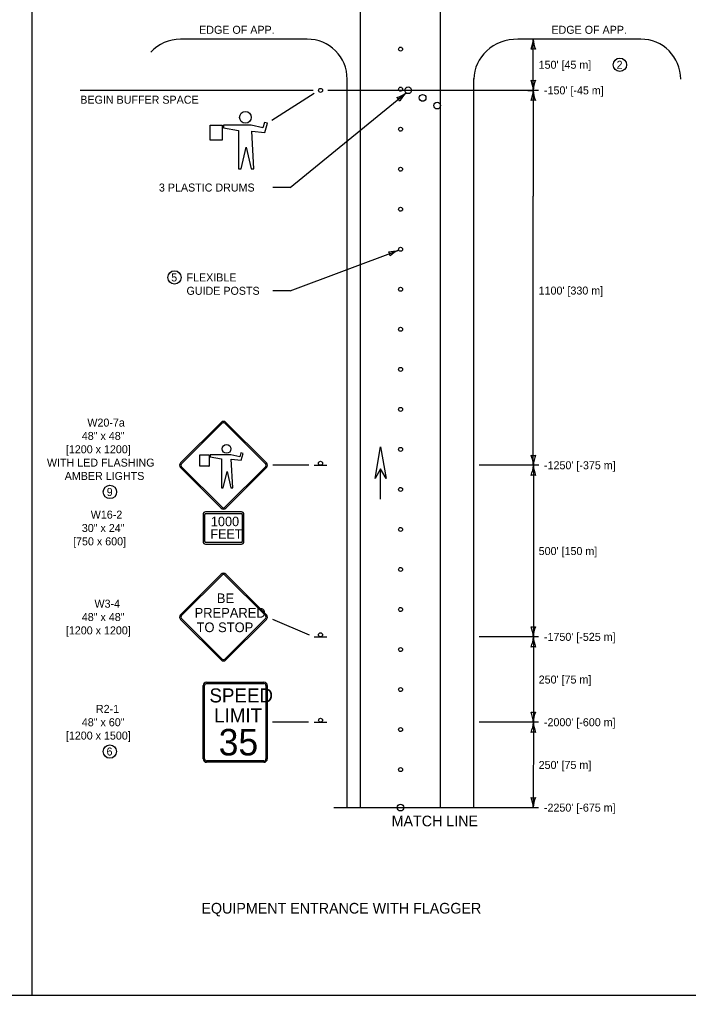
# Model space of a CAD drawing. Extents: x 49991.4 to 50021, y 49987.6 to 50011.4.
# Drawn here: x 50009.09 to 50014.11, y 49987.8 to 49995.11 of the extents above; entities that cross this region are included whole.
import ezdxf

# ---------------------------------------------------------------- set-up
doc = ezdxf.new("R2010")
doc.units = 0
for name, color, linetype in [('Level 1', 7, 'Continuous'), ('Level 2', 7, 'Continuous'), ('Level 3', 7, 'Continuous'), ('Level 6', 7, 'Continuous')]:
    doc.layers.add(name, color=color, linetype=linetype)

msp = doc.modelspace()

# ---------------------------------------------------------------- linework, layer by layer
at = {"layer": 'Level 1'}
for p, q in [((50011.6491, 49989.2068), (50011.6491, 49998.1941)), ((50012.2491, 49989.2068), (50012.2491, 49998.1941)), ((50011.2489, 49994.9668), (50010.2983, 49994.9668)), ((50013.7497, 49994.9668), (50012.8291, 49994.9668)), ((50011.5491, 49989.2068), (50011.5491, 49994.6668)), ((50012.4991, 49989.2068), (50012.4991, 49994.6713)), ((50010.5205, 49994.2099), (50010.5205, 49994.3224)), ((50010.5205, 49994.3224), (50010.6124, 49994.3224)), ((50010.6124, 49994.3224), (50010.6124, 49994.2099)), ((50010.8296, 49994.3217), (50010.6227, 49994.3217)), ((50010.6227, 49994.3217), (50010.6227, 49994.3031)), ((50010.6227, 49994.3031), (50010.7352, 49994.2809)), ((50010.7352, 49994.2809), (50010.7352, 49993.9946)), ((50010.9164, 49994.3017), (50010.8296, 49994.3217)), ((50010.8483, 49993.9946), (50010.8335, 49994.278)), ((50010.8335, 49994.278), (50010.9311, 49994.267)), ((50010.9291, 49994.3413), (50010.9164, 49994.3017)), ((50010.9511, 49994.3358), (50010.9291, 49994.3413)), ((50010.9311, 49994.267), (50010.9511, 49994.3358)), ((50010.6124, 49994.2099), (50010.5205, 49994.2099)), ((50010.7534, 49993.9946), (50010.7917, 49994.1559)), ((50010.7917, 49994.1559), (50010.83, 49993.9946)), ((50010.7352, 49993.9946), (50010.7534, 49993.9946)), ((50010.83, 49993.9946), (50010.8483, 49993.9946)), ((50010.6042, 49992.0945), (50010.3001, 49991.7905)), ((50010.6112, 49992.0875), (50010.3072, 49991.7834)), ((50010.9365, 49991.7834), (50010.6325, 49992.0875)), ((50010.9436, 49991.7905), (50010.6395, 49992.0945)), ((50010.7525, 49991.8662), (50010.7429, 49991.8362)), ((50010.7691, 49991.862), (50010.7525, 49991.8662)), ((50010.4435, 49991.7668), (50010.4435, 49991.8518)), ((50010.4435, 49991.8518), (50010.513, 49991.8518)), ((50010.513, 49991.8518), (50010.513, 49991.7668)), ((50010.6773, 49991.8514), (50010.5208, 49991.8514)), ((50010.5208, 49991.8514), (50010.5208, 49991.8373)), ((50010.5208, 49991.8373), (50010.6058, 49991.8205)), ((50010.6058, 49991.8205), (50010.6058, 49991.604)), ((50010.7429, 49991.8362), (50010.6773, 49991.8514)), ((50010.6913, 49991.604), (50010.6801, 49991.8183)), ((50010.6801, 49991.8183), (50010.754, 49991.81)), ((50010.754, 49991.81), (50010.7691, 49991.862)), ((50010.3001, 49991.7551), (50010.6042, 49991.4511)), ((50010.3072, 49991.7622), (50010.6112, 49991.4581)), ((50010.513, 49991.7668), (50010.4435, 49991.7668)), ((50010.6196, 49991.604), (50010.6485, 49991.726)), ((50010.6325, 49991.4581), (50010.9365, 49991.7622)), ((50010.6395, 49991.4511), (50010.9436, 49991.7551)), ((50010.6485, 49991.726), (50010.6775, 49991.604)), ((50011.301, 49991.7728), (50011.397, 49991.7728)), ((50011.7994, 49991.5199), (50011.7994, 49991.7458)), ((50011.7997, 49991.5199), (50011.7997, 49991.7458)), ((50010.6058, 49991.604), (50010.6196, 49991.604)), ((50010.6775, 49991.604), (50010.6913, 49991.604)), ((50010.7559, 49991.4237), (50010.4878, 49991.4237)), ((50010.4686, 49991.4035), (50010.4686, 49991.2019)), ((50010.4814, 49991.2019), (50010.4814, 49991.4035)), ((50010.4878, 49991.4102), (50010.7559, 49991.4102)), ((50010.7623, 49991.4035), (50010.7623, 49991.2019)), ((50010.7751, 49991.2019), (50010.7751, 49991.4035)), ((50010.7559, 49991.1952), (50010.4878, 49991.1952)), ((50010.4878, 49991.1817), (50010.7559, 49991.1817)), ((50010.3002, 49990.6528), (50010.6043, 49990.9568)), ((50010.3073, 49990.6457), (50010.6113, 49990.9498)), ((50010.6326, 49990.9498), (50010.9366, 49990.6457)), ((50010.6396, 49990.9568), (50010.9437, 49990.6528)), ((50010.6113, 49990.3204), (50010.3073, 49990.6245)), ((50010.9366, 49990.6245), (50010.6326, 49990.3204)), ((50010.6043, 49990.3134), (50010.3002, 49990.6174)), ((50010.9437, 49990.6174), (50010.6396, 49990.3134)), ((50011.301, 49990.4868), (50011.397, 49990.4868)), ((50010.47, 49989.5718), (50010.47, 49990.1218)), ((50010.48, 49989.5718), (50010.48, 49990.1218)), ((50010.495, 49990.1468), (50010.925, 49990.1468)), ((50010.495, 49990.1368), (50010.925, 49990.1368)), ((50010.94, 49990.1218), (50010.94, 49989.5718)), ((50010.95, 49990.1218), (50010.95, 49989.5718)), ((50011.3011, 49989.8468), (50011.3971, 49989.8468)), ((50010.925, 49989.5568), (50010.495, 49989.5568)), ((50010.925, 49989.5468), (50010.495, 49989.5468))]:
    msp.add_line(p, q, dxfattribs=at)
for points in [[(49999.3835, 49998.9992), (50016.7501, 49998.9992), (50016.7501, 49987.7988), (49999.3835, 49987.7988)], [(50011.7577, 49991.6735), (50011.7994, 49991.91), (50011.8413, 49991.6735), (50011.7994, 49991.7457)]]:
    msp.add_lwpolyline(points, close=True, dxfattribs=at)
for points in [[(50010.929, 49994.3411), (50010.9292, 49994.3413)], [(50010.612, 49994.2099), (50010.6124, 49994.2103)], [(50010.9305, 49994.2671), (50010.9314, 49994.2682)], [(50010.7524, 49991.866), (50010.7525, 49991.8662)], [(50010.7535, 49991.8101), (50010.7542, 49991.8109)], [(50010.5127, 49991.7668), (50010.513, 49991.7671)]]:
    msp.add_lwpolyline(points, dxfattribs=at)
for centre, radius in [((50011.9491, 49994.8918), 0.015), ((50011.3491, 49994.5828), 0.0152), ((50011.9491, 49994.5918), 0.015), ((50012.0066, 49994.5832), 0.025), ((50012.1148, 49994.5259), 0.025), ((50010.786, 49994.3805), 0.0442), ((50012.2231, 49994.4685), 0.025), ((50011.9491, 49994.2918), 0.015), ((50011.9491, 49993.9918), 0.015), ((50011.9491, 49993.6918), 0.015), ((50011.9491, 49993.3918), 0.015), ((50011.9491, 49993.0918), 0.015), ((50011.9491, 49992.7918), 0.015), ((50011.9491, 49992.4918), 0.015), ((50011.9491, 49992.1918), 0.015), ((50010.6442, 49991.8958), 0.0334), ((50011.9491, 49991.8918), 0.015), ((50011.349, 49991.788), 0.0152), ((50011.9491, 49991.5918), 0.015), ((50011.9491, 49991.2918), 0.015), ((50011.9491, 49990.9918), 0.015), ((50011.9491, 49990.6918), 0.015), ((50011.349, 49990.502), 0.0152), ((50011.9491, 49990.3918), 0.015), ((50011.9491, 49990.0918), 0.015), ((50011.3491, 49989.862), 0.0152), ((50011.9491, 49989.7918), 0.015), ((50011.9491, 49989.4918), 0.015), ((50011.9491, 49989.2068), 0.025)]:
    msp.add_circle(centre, radius, dxfattribs=at)
for centre, radius, start, end in [((50010.2983, 49994.6668), 0.3, 90, 137.78002), ((50011.2489, 49994.6668), 0.3, 0, 90), ((50013.7497, 49994.6668), 0.3, 0, 90), ((50010.6218, 49992.0769), 0.025, 45, 135), ((50010.6218, 49992.0769), 0.015, 45, 135), ((50010.3178, 49991.7728), 0.025, 135, 225), ((50010.9259, 49991.7728), 0.025, 315, 45.00024), ((50010.3178, 49991.7728), 0.015, 135, 225), ((50010.9259, 49991.7728), 0.015, 315, 45.00024), ((50010.6218, 49991.4687), 0.025, 225, 314.99957), ((50010.6218, 49991.4687), 0.015, 225, 314.99957), ((50010.6219, 49990.9392), 0.025, 45, 135), ((50010.6219, 49990.9392), 0.015, 45, 135), ((50010.3178, 49990.6352), 0.025, 134.99976, 225), ((50010.3178, 49990.6352), 0.015, 134.99976, 225), ((50010.926, 49990.6352), 0.015, 315, 45), ((50010.926, 49990.6352), 0.025, 315, 45), ((50010.6219, 49990.3311), 0.025, 225.00043, 315), ((50010.6219, 49990.3311), 0.015, 225.00043, 315), ((50010.495, 49990.1218), 0.025, 90, 180), ((50010.495, 49990.1218), 0.015, 90, 180), ((50010.925, 49990.1218), 0.025, 0, 90), ((50010.925, 49990.1218), 0.015, 0, 90), ((50010.495, 49989.5718), 0.025, 180, 270), ((50010.495, 49989.5718), 0.015, 180, 270), ((50010.925, 49989.5718), 0.025, 270, 0), ((50010.925, 49989.5718), 0.015, 270, 0)]:
    msp.add_arc(centre, radius, start, end, dxfattribs=at)
for centre, major_axis, ratio, start_param, end_param in [((50012.8291, 49994.6668), (-0.33, 0), 0.909033, 4.712389, 6.283185), ((50010.4878, 49991.4035), (0, 0.0202), 0.95, 0, 1.570796), ((50010.7559, 49991.4035), (0, 0.0202), 0.95, 4.712389, 6.283185), ((50010.4878, 49991.4035), (0, 0.00672), 0.95, 0, 1.570796), ((50010.7559, 49991.4035), (0, 0.00672), 0.95, 4.712389, 6.283185), ((50010.4878, 49991.2019), (0, -0.0202), 0.95, 4.712389, 6.283185), ((50010.4878, 49991.2019), (0, -0.00672), 0.95, 4.712389, 6.283185), ((50010.7559, 49991.2019), (0, -0.00672), 0.95, 0, 1.570796), ((50010.7559, 49991.2019), (0, -0.0202), 0.95, 0, 1.570796)]:
    msp.add_ellipse(centre, major_axis=major_axis, ratio=ratio, start_param=start_param, end_param=end_param, dxfattribs=at)
at = {"layer": 'Level 2'}
for centre in [(50013.5938, 49994.7748), (50010.2543, 49993.1806), (50009.7705, 49991.5727), (50009.7692, 49989.6272)]:
    msp.add_circle(centre, 0.05, dxfattribs=at)
at = {"layer": 'Level 3'}
for p, q in [((50009.1835, 49998.9992), (50009.1835, 49987.7988)), ((50012.9443, 49994.5828), (50012.9443, 49994.9668)), ((50011.2939, 49994.5828), (50009.5479, 49994.5828)), ((50012.9843, 49994.5828), (50011.4044, 49994.5828)), ((50012.9043, 49994.5828), (50012.9443, 49994.5828)), ((50012.9443, 49994.5828), (50012.9443, 49993.7891)), ((50011.3015, 49994.5593), (50010.985, 49994.3571)), ((50011.1222, 49993.8545), (50011.9909, 49994.5638)), ((50011.1222, 49993.8545), (50010.9911, 49993.8545)), ((50012.9443, 49991.7728), (50012.9443, 49993.7891)), ((50011.1222, 49993.0806), (50011.9353, 49993.3861)), ((50011.1222, 49993.0806), (50010.9911, 49993.0806)), ((50011.261, 49991.7728), (50010.9909, 49991.7728)), ((50012.9846, 49991.7728), (50012.5391, 49991.7728)), ((50012.9448, 49991.7728), (50012.9448, 49990.4868)), ((50010.9878, 49990.6196), (50011.2641, 49990.5024)), ((50012.9841, 49990.4868), (50012.5391, 49990.4868)), ((50012.9448, 49990.4868), (50012.9448, 49989.8468)), ((50011.26, 49989.8468), (50010.99, 49989.8468)), ((50012.9841, 49989.8468), (50012.5391, 49989.8468)), ((50012.9448, 49989.8468), (50012.9441, 49989.2068))]:
    msp.add_line(p, q, dxfattribs=at)
for centre, radius, start, end in [((50012.7222, 49994.976), 0.2223, 337.45601, 357.63952), ((50013.177, 49994.9783), 0.233, 182.82731, 202.07716), ((50012.9443, 49994.8386), 0.0548, 72.13882, 107.86118), ((50012.9443, 49994.711), 0.0548, 252.13882, 287.86118), ((50012.7116, 49994.5713), 0.233, 2.82731, 22.07716), ((50013.1664, 49994.5736), 0.2223, 157.45601, 177.63952), ((50012.7116, 49994.5943), 0.233, 337.92284, 357.17269), ((50013.1664, 49994.592), 0.2223, 182.36048, 202.54399), ((50011.8575, 49994.7416), 0.2223, 286.68743, 306.87094), ((50011.8916, 49994.4827), 0.0548, 21.37024, 57.0926), ((50012.147, 49994.3908), 0.233, 132.05873, 151.30858), ((50012.9443, 49994.4546), 0.0548, 72.13882, 107.86118), ((50011.8619, 49993.5959), 0.2223, 269.09342, 289.27693), ((50011.8161, 49993.3388), 0.0548, 3.77623, 39.49859), ((50012.0318, 49993.174), 0.233, 114.46472, 133.71457), ((50012.7225, 49991.7639), 0.2223, 2.36048, 22.54399), ((50012.9446, 49991.9012), 0.0548, 252.13882, 287.86118), ((50013.1773, 49991.7615), 0.233, 157.92284, 177.17269), ((50012.7225, 49991.7818), 0.2223, 337.45601, 357.63952), ((50013.1773, 49991.7841), 0.233, 182.82731, 202.07716), ((50012.9446, 49991.6444), 0.0548, 72.13882, 107.86118), ((50012.9441, 49990.6152), 0.0548, 252.13882, 287.86118), ((50012.7114, 49990.4755), 0.233, 2.82731, 22.07716), ((50013.1662, 49990.4779), 0.2223, 157.45601, 177.63952), ((50012.7225, 49990.4958), 0.2223, 337.45601, 357.63952), ((50013.1773, 49990.4981), 0.233, 182.82731, 202.07716), ((50012.9446, 49990.3584), 0.0548, 72.13882, 107.86118), ((50012.9441, 49989.9752), 0.0548, 252.13882, 287.86118), ((50012.7114, 49989.8355), 0.233, 2.82731, 22.07716), ((50013.1662, 49989.8379), 0.2223, 157.45601, 177.63952), ((50012.7225, 49989.8558), 0.2223, 337.45601, 357.63952), ((50013.1773, 49989.8581), 0.233, 182.82731, 202.07716), ((50012.9446, 49989.7184), 0.0548, 72.13882, 107.86118), ((50012.9441, 49989.3352), 0.0548, 252.13882, 287.86118), ((50012.7114, 49989.1955), 0.233, 2.82731, 22.07716), ((50013.1662, 49989.1979), 0.2223, 157.45601, 177.63952)]:
    msp.add_arc(centre, radius, start, end, dxfattribs=at)
at = {"layer": 'Level 6'}
msp.add_line((50011.4491, 49989.2068), (50012.9841, 49989.2068), dxfattribs=at)

# ---------------------------------------------------------------- texts
at = {"layer": 'Level 1'}
for s, height, p in [('1000', 0.07124, (50010.5268, 49991.3161)), ('FEET', 0.06989, (50010.5238, 49991.222)), ('BE', 0.0725, (50010.5716, 49990.7396)), ('PREPARED', 0.0725, (50010.4047, 49990.6308)), ('TO STOP', 0.0725, (50010.4195, 49990.5221)), ('SPEED', 0.10512, (50010.5162, 49989.9952)), ('LIMIT', 0.10512, (50010.5516, 49989.8451)), ('35', 0.19892, (50010.5856, 49989.5978))]:
    msp.add_text(s, height=height, dxfattribs=at).set_placement(p)
at = {"layer": 'Level 2'}
for s, height, p in [('EDGE OF APP.', 0.06, (50010.4389, 49995.0068)), ('EDGE OF APP.', 0.06, (50013.0802, 49995.0068)), ("150' [45 m]", 0.06, (50012.9843, 49994.7448)), ('2', 0.06, (50013.5687, 49994.7448)), ("-150' [-45 m]", 0.06, (50013.0243, 49994.5528)), ('BEGIN BUFFER SPACE', 0.06, (50009.5479, 49994.4828)), ('3 PLASTIC DRUMS', 0.06, (50010.1373, 49993.8245)), ('5', 0.06, (50010.2294, 49993.1506)), ('FLEXIBLE', 0.06, (50010.3443, 49993.1506)), ('GUIDE POSTS', 0.06, (50010.3443, 49993.0506)), ("1100' [330 m]", 0.06, (50012.9843, 49993.0523)), ('W20-7a', 0.06, (50009.6008, 49992.0627)), ('48" x 48"', 0.06, (50009.5593, 49991.9627)), ('[1200 x 1200]', 0.06, (50009.4399, 49991.8627)), ('WITH LED FLASHING', 0.06, (50009.2977, 49991.7627)), ("-1250' [-375 m]", 0.06, (50013.0246, 49991.7428)), ('AMBER LIGHTS', 0.06, (50009.4308, 49991.6627)), ('9', 0.06, (50009.7459, 49991.5427)), ('W16-2', 0.06, (50009.6262, 49991.3727)), ('30" x 24"', 0.06, (50009.5593, 49991.2727)), ('[750 x 600]', 0.06, (50009.4938, 49991.1727)), ("500' [150 m]", 0.06, (50012.9848, 49991.0998)), ('W3-4', 0.06, (50009.6543, 49990.7052)), ('48" x 48"', 0.06, (50009.5593, 49990.6052)), ('[1200 x 1200]', 0.06, (50009.4399, 49990.5052)), ("-1750' [-525 m]", 0.06, (50013.0241, 49990.4568)), ("250' [75 m]", 0.06, (50012.9848, 49990.1368)), ('R2-1', 0.06, (50009.6649, 49989.9168)), ('48" x 60"', 0.06, (50009.5593, 49989.8168)), ("-2000' [-600 m]", 0.06, (50013.0241, 49989.8168)), ('[1200 x 1500]', 0.06, (50009.4399, 49989.7168)), ('6', 0.06, (50009.7447, 49989.5972)), ("250' [75 m]", 0.06, (50012.9845, 49989.4968)), ("-2250' [-675 m]", 0.06, (50013.0241, 49989.1768)), ('MATCH LINE', 0.08, (50011.8821, 49989.0668)), ('EQUIPMENT ENTRANCE WITH FLAGGER', 0.08, (50010.4562, 49988.4127))]:
    msp.add_text(s, height=height, dxfattribs=at).set_placement(p)

doc.saveas('drawing.dxf')
